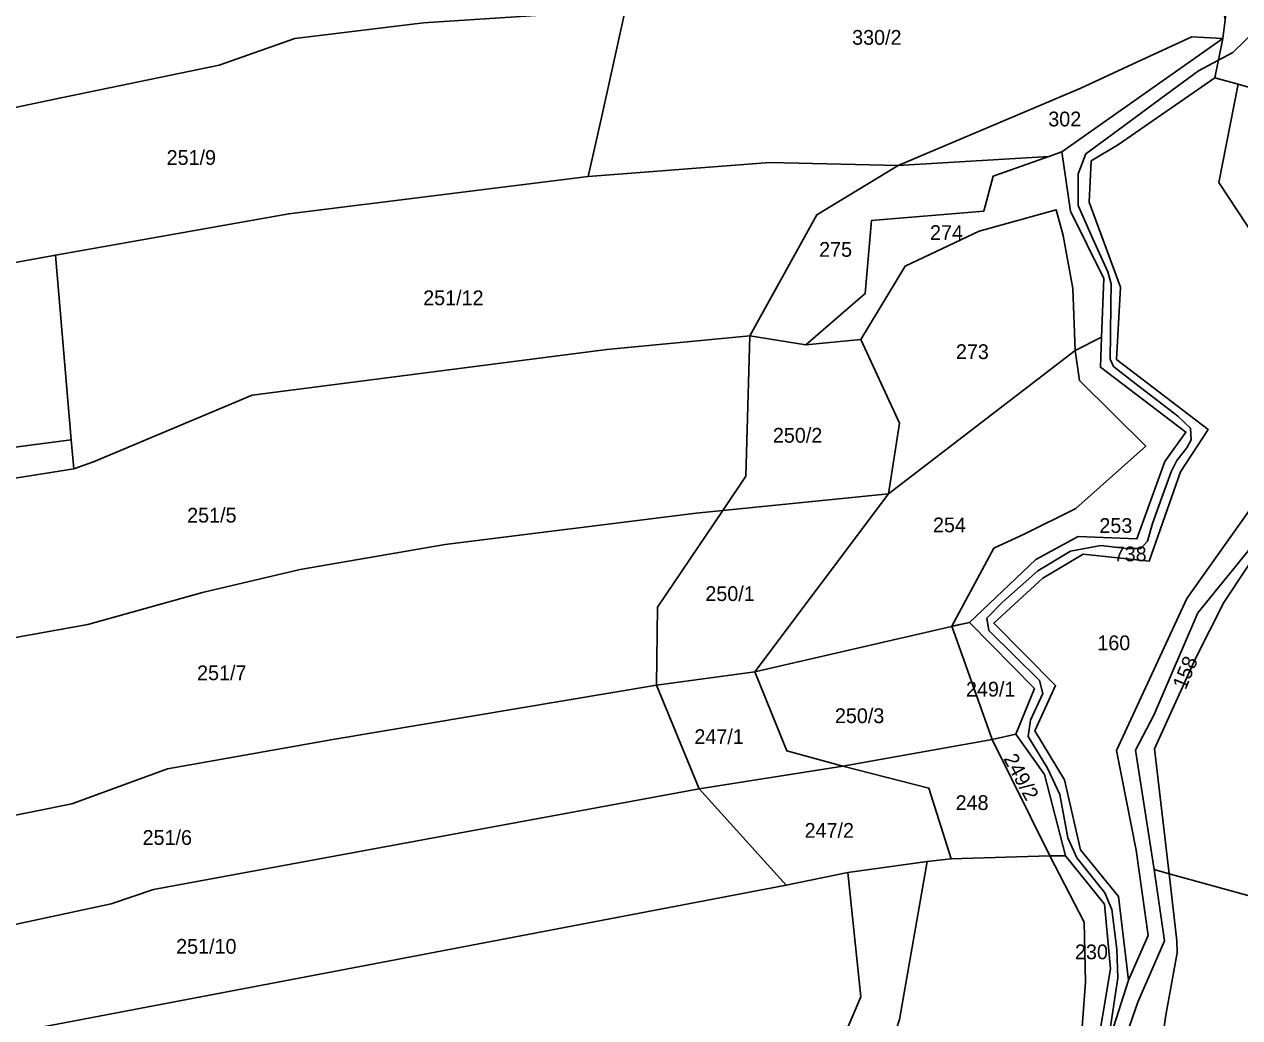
# Model space of a CAD drawing. Extents: x -629983 to -626385, y -1072828 to -1067897.
# Drawn here: x -627910.7 to -627663.6, y -1071057.2 to -1070855.3 of the extents above; entities that cross this region are included whole.
import ezdxf

# ---------------------------------------------------------------- set-up
doc = ezdxf.new("R2010")
doc.units = 0
for name, color, linetype in [('Lesy', 7, 'Continuous'), ('Parcela nároku', 7, 'Continuous'), ('Parcelní číslo', 7, 'Continuous'), ('Plocha PÚ', 7, 'Continuous'), ('Vnitřní obvod_šetřený', 7, 'Continuous'), ('voda', 7, 'Continuous')]:
    doc.layers.add(name, color=color, linetype=linetype)

msp = doc.modelspace()

# ---------------------------------------------------------------- linework, layer by layer
at = {"layer": 'Lesy'}
for p, q in [((-627702.4, -1070882.17), (-627733.04, -1070884.02)), ((-627713.9, -1071000.65), (-627709.08, -1070999.61))]:
    msp.add_line(p, q, dxfattribs=at)
for points in [[(-627763.16, -1070918.66), (-627751.82, -1070920.47), (-627739.75, -1070910.01), (-627738.41, -1070895.18), (-627715.62, -1070893.28), (-627713.72, -1070886.19), (-627702.4, -1070882.17), (-627699.77, -1070881.23)], [(-627768.7, -1070954.14), (-627734.96, -1070950.75), (-627697.03, -1070921.6), (-627691.66, -1070918.93)], [(-627782.13, -1070989.61), (-627762.15, -1070986.91), (-627722.2, -1070977.69), (-627718.53, -1070976.9)], [(-627773.5, -1071010.68), (-627744.25, -1071006.08), (-627713.9, -1071000.65)], [(-627699.02, -1071024.34), (-627702.18, -1071024.34), (-627722.26, -1071024.91), (-627727.14, -1071025.51), (-627743.28, -1071027.73)]]:
    msp.add_lwpolyline(points, dxfattribs=at)
at = {"layer": 'Parcela nároku'}
for points in [[(-627776.03, -1070817.67), (-627781.03, -1070818.65), (-627781.59, -1070821.17), (-627788.59, -1070852.77), (-627793.29, -1070873.99), (-627796.08, -1070886.23), (-627759.08, -1070883.39), (-627733.04, -1070884.02), (-627695.86, -1070868.29), (-627684.37, -1070862.94), (-627673.34, -1070857.87), (-627667.02, -1070858.18), (-627666.57, -1070854.4), (-627669.26, -1070837.49), (-627680.55, -1070832.34), (-627686.39, -1070830.88), (-627692.88, -1070830.18), (-627693.06, -1070825.67), (-627704.19, -1070823.07), (-627730.21, -1070817.05), (-627744.9, -1070815.04)], [(-627801.49, -1070822.34), (-627781.59, -1070821.17), (-627788.59, -1070852.77), (-627795.23, -1070852.8), (-627829.54, -1070855.03), (-627855.66, -1070858.18), (-627871.1, -1070863.63), (-627903.55, -1070870.3), (-627965.1, -1070883.25), (-627964.44, -1070878.78), (-627949.1, -1070853.24), (-627939.64, -1070842.36), (-627915.75, -1070837.66), (-627910.72, -1070836.78), (-627868.6, -1070829.4), (-627844.7, -1070826.54), (-627829.74, -1070827.42), (-627824.59, -1070826.82), (-627818.12, -1070823.77)], [(-627969.54, -1070913.45), (-627965.1, -1070883.25), (-627903.55, -1070870.3), (-627871.1, -1070863.63), (-627855.66, -1070858.18), (-627829.54, -1070855.03), (-627795.23, -1070852.8), (-627788.59, -1070852.77), (-627793.29, -1070873.99), (-627796.08, -1070886.23), (-627856.91, -1070893.83), (-627904.38, -1070902.22), (-627956.41, -1070911.75), (-627967.36, -1070913.5)], [(-627684.37, -1070862.94), (-627673.34, -1070857.87), (-627667.02, -1070858.18), (-627699.77, -1070881.23), (-627702.4, -1070882.17), (-627733.04, -1070884.02), (-627695.86, -1070868.29)], [(-627709.08, -1070999.61), (-627705.31, -1070990.3), (-627718.53, -1070976.9), (-627705.04, -1070964.09), (-627696.41, -1070959.41), (-627684.49, -1070959.86), (-627678.83, -1070944.19), (-627674.53, -1070938.2), (-627691.89, -1070925.02), (-627691.66, -1070918.93), (-627691.21, -1070906.96), (-627697.95, -1070893.27), (-627699.77, -1070881.23), (-627667.02, -1070858.18), (-627668.65, -1070866.2), (-627688.23, -1070879.74), (-627693.76, -1070883.07), (-627694.19, -1070891.48), (-627687.81, -1070908.71), (-627688.65, -1070923.45), (-627670, -1070937.7), (-627675.65, -1070946.29), (-627682.02, -1070964.46), (-627695.43, -1070963.01), (-627703.62, -1070967.89), (-627713.58, -1070977.02), (-627701.03, -1070989.72), (-627705.23, -1070998.92), (-627699.23, -1071008.89), (-627695.93, -1071023.12), (-627688.23, -1071032.59), (-627686.17, -1071049.62), (-627694.72, -1071076.38), (-627689.88, -1071047.31), (-627691.1, -1071034.14), (-627699.02, -1071024.34), (-627703.25, -1071007.78)], [(-627702.4, -1070882.17), (-627699.77, -1070881.23), (-627697.95, -1070893.27), (-627691.21, -1070906.96), (-627691.66, -1070918.93), (-627697.03, -1070921.6), (-627697.5, -1070908.99), (-627699.46, -1070898.26), (-627700.87, -1070893), (-627716.55, -1070897.35), (-627731.61, -1070904.46), (-627740.6, -1070919.36), (-627751.82, -1070920.47), (-627739.75, -1070910.01), (-627738.41, -1070895.18), (-627715.62, -1070893.28), (-627713.72, -1070886.19)], [(-627904.38, -1070902.22), (-627856.91, -1070893.83), (-627796.08, -1070886.23), (-627759.08, -1070883.39), (-627733.04, -1070884.02), (-627749.57, -1070894.02), (-627763.16, -1070918.66), (-627792.28, -1070921.41), (-627864.34, -1070930.66), (-627896.65, -1070944.27), (-627900.65, -1070945.66), (-627901.16, -1070939.77)], [(-627733.04, -1070884.02), (-627702.4, -1070882.17), (-627713.72, -1070886.19), (-627715.62, -1070893.28), (-627738.41, -1070895.18), (-627739.75, -1070910.01), (-627751.82, -1070920.47), (-627763.16, -1070918.66), (-627749.57, -1070894.02)], [(-627699.46, -1070898.26), (-627697.5, -1070908.99), (-627697.03, -1070921.6), (-627734.96, -1070950.75), (-627732.72, -1070936.39), (-627740.6, -1070919.36), (-627731.61, -1070904.46), (-627716.55, -1070897.35), (-627700.87, -1070893)], [(-627904.38, -1070902.22), (-627901.16, -1070939.77), (-627964.42, -1070948.04), (-627965.93, -1070922.44), (-627954.97, -1070920.68), (-627956.41, -1070911.75)], [(-627864.34, -1070930.66), (-627792.28, -1070921.41), (-627763.16, -1070918.66), (-627764.01, -1070947.18), (-627768.7, -1070954.14), (-627774.12, -1070954.69), (-627825.12, -1070961.06), (-627854.63, -1070966.13), (-627874.47, -1070970.81), (-627897.8, -1070977.31), (-627975.92, -1070991.3), (-627973.38, -1070957.36), (-627964.22, -1070955.75), (-627900.65, -1070945.66), (-627896.65, -1070944.27)], [(-627763.16, -1070918.66), (-627751.82, -1070920.47), (-627740.6, -1070919.36), (-627732.72, -1070936.39), (-627734.96, -1070950.75), (-627768.7, -1070954.14), (-627764.01, -1070947.18)], [(-627674.53, -1070938.2), (-627691.89, -1070925.02), (-627691.66, -1070918.93), (-627697.03, -1070921.6), (-627696.16, -1070927.73), (-627682.68, -1070941.05), (-627696.9, -1070953.7), (-627707.27, -1070958.89), (-627713.55, -1070961.76), (-627722.08, -1070977.63), (-627718.53, -1070976.9), (-627705.04, -1070964.09), (-627696.41, -1070959.41), (-627684.49, -1070959.86), (-627678.83, -1070944.19)], [(-627697.03, -1070921.6), (-627696.16, -1070927.73), (-627682.68, -1070941.05), (-627696.9, -1070953.7), (-627707.27, -1070958.89), (-627713.55, -1070961.76), (-627722.08, -1070977.63), (-627722.2, -1070977.69), (-627762.15, -1070986.91), (-627734.96, -1070950.75)], [(-627633.04, -1070934.28), (-627629.23, -1070934.48), (-627610.1, -1070939.85), (-627595.94, -1070943.82), (-627593.56, -1070944.49), (-627607.17, -1070975.87), (-627608.65, -1070982.03), (-627608.85, -1070996.03), (-627589.14, -1071052.37), (-627677.94, -1071028.02), (-627680.89, -1071002.55), (-627672.57, -1070984.19), (-627666.8, -1070972.82), (-627648.36, -1070945.08), (-627646.91, -1070943.45), (-627646.35, -1070936.1)], [(-627901.16, -1070939.77), (-627964.42, -1070948.04), (-627964.22, -1070955.75), (-627900.65, -1070945.66)], [(-627681.06, -1070995.72), (-627672.12, -1070974.94), (-627660.33, -1070960.45), (-627648.36, -1070945.08), (-627666.8, -1070972.82), (-627672.57, -1070984.19), (-627680.89, -1071002.55), (-627677.94, -1071028.02), (-627680.98, -1071027.09), (-627684.77, -1071002.85)], [(-627782.13, -1070989.61), (-627781.92, -1070973.76), (-627768.7, -1070954.14), (-627734.96, -1070950.75), (-627762.15, -1070986.91)], [(-627854.63, -1070966.13), (-627874.47, -1070970.81), (-627897.8, -1070977.31), (-627975.92, -1070991.3), (-627978.19, -1071021.66), (-627978.7, -1071031.04), (-627948.79, -1071023.35), (-627901.04, -1071013.77), (-627881.56, -1071006.67), (-627847.96, -1071000.67), (-627782.13, -1070989.61), (-627781.92, -1070973.76), (-627768.7, -1070954.14), (-627774.12, -1070954.69), (-627825.12, -1070961.06)], [(-627762.15, -1070986.91), (-627722.2, -1070977.69), (-627722.08, -1070977.63), (-627713.9, -1071000.65), (-627744.25, -1071006.08), (-627755.63, -1071003.01)], [(-627705.31, -1070990.3), (-627718.53, -1070976.9), (-627722.08, -1070977.63), (-627713.9, -1071000.65), (-627709.08, -1070999.61)], [(-627782.13, -1070989.61), (-627762.15, -1070986.91), (-627755.63, -1071003.01), (-627744.25, -1071006.08), (-627773.5, -1071010.68)], [(-627773.5, -1071010.68), (-627782.13, -1070989.61), (-627847.96, -1071000.67), (-627881.56, -1071006.67), (-627901.04, -1071013.77), (-627948.79, -1071023.35), (-627978.7, -1071031.04), (-627979.88, -1071052.75), (-627893.02, -1071034.08), (-627884.41, -1071031.17)], [(-627713.9, -1071000.65), (-627702.18, -1071024.34), (-627722.26, -1071024.91), (-627726.76, -1071010.57), (-627744.25, -1071006.08)], [(-627713.9, -1071000.65), (-627709.08, -1070999.61), (-627703.25, -1071007.78), (-627699.02, -1071024.34), (-627702.18, -1071024.34)], [(-627726.76, -1071010.57), (-627722.26, -1071024.91), (-627727.14, -1071025.51), (-627743.28, -1071027.73), (-627755.81, -1071030.27), (-627773.5, -1071010.68), (-627744.25, -1071006.08)], [(-627884.41, -1071031.17), (-627773.5, -1071010.68), (-627755.81, -1071030.27), (-627842.41, -1071046.8), (-627980.99, -1071073.17), (-627979.88, -1071052.75), (-627893.02, -1071034.08)], [(-627732.76, -1071057.61), (-627742.21, -1071086.89), (-627740.95, -1071096.51), (-627718.37, -1071093.78), (-627697.75, -1071094.07), (-627697.26, -1071080.89), (-627694.91, -1071049.98), (-627695.21, -1071037.83), (-627702.18, -1071024.34), (-627722.26, -1071024.91), (-627727.14, -1071025.51)], [(-627694.91, -1071049.98), (-627697.26, -1071080.89), (-627694.72, -1071076.38), (-627689.88, -1071047.31), (-627691.1, -1071034.14), (-627699.02, -1071024.34), (-627702.18, -1071024.34), (-627695.21, -1071037.83)], [(-627990.6, -1071134.13), (-627983.67, -1071096.07), (-627981.04, -1071074.18), (-627980.99, -1071073.17), (-627842.41, -1071046.8), (-627755.81, -1071030.27), (-627743.28, -1071027.73), (-627740.61, -1071053.02), (-627750.22, -1071075.54), (-627752.84, -1071100.75), (-627875.8, -1071126.47), (-627933.16, -1071141.74), (-627995.06, -1071154.04)], [(-627742.21, -1071086.89), (-627740.95, -1071096.51), (-627752.84, -1071100.75), (-627750.22, -1071075.54), (-627740.61, -1071053.02), (-627743.28, -1071027.73), (-627727.14, -1071025.51), (-627732.76, -1071057.61)], [(-627538.56, -1071194.21), (-627524.91, -1071234.88), (-627555.07, -1071238.31), (-627565.67, -1071214.8), (-627570.33, -1071210.92), (-627571.88, -1071209.62), (-627592.75, -1071192.23), (-627608.51, -1071161.77), (-627619.56, -1071140.72), (-627630.41, -1071134.09), (-627635.39, -1071116.68), (-627654.32, -1071103.18), (-627673.05, -1071079.5), (-627680.55, -1071070.62), (-627678.61, -1071056.69), (-627676.31, -1071044.06), (-627676.33, -1071041.64), (-627677.94, -1071028.02), (-627589.14, -1071052.37), (-627581.22, -1071076.02), (-627572.29, -1071106.16), (-627556.31, -1071148.68), (-627546.27, -1071173.51)]]:
    msp.add_lwpolyline(points, close=True, dxfattribs=at)
for points in [[(-627663.44, -1070819.25), (-627665.7, -1070829.55), (-627663.7, -1070828.83), (-627666.57, -1070854.4), (-627667.02, -1070858.18), (-627668.65, -1070866.2), (-627663.91, -1070867.45), (-627660.19, -1070868.57)], [(-627660.36, -1070898.79), (-627667.8, -1070887.49), (-627663.91, -1070867.45), (-627668.65, -1070866.2), (-627688.23, -1070879.74), (-627693.76, -1070883.07), (-627694.19, -1070891.48), (-627687.81, -1070908.71), (-627688.65, -1070923.45), (-627670, -1070937.7), (-627675.65, -1070946.29), (-627682.02, -1070964.46), (-627695.43, -1070963.01), (-627703.62, -1070967.89), (-627713.58, -1070977.02), (-627701.03, -1070989.72), (-627705.23, -1070998.92), (-627699.23, -1071008.89), (-627695.93, -1071023.12), (-627688.23, -1071032.59), (-627686.17, -1071049.62), (-627682.2, -1071040.54), (-627684.63, -1071023.21), (-627688.6, -1071002.91), (-627674.3, -1070972.05), (-627652.45, -1070941.16)], [(-627660.36, -1070898.79), (-627667.8, -1070887.49), (-627663.91, -1070867.45), (-627660.19, -1070868.57)], [(-627694.72, -1071076.38), (-627686.17, -1071049.62), (-627682.2, -1071040.54), (-627684.63, -1071023.21), (-627688.6, -1071002.91), (-627674.3, -1070972.05), (-627652.45, -1070941.16)], [(-627660.33, -1070960.45), (-627672.12, -1070974.94), (-627681.06, -1070995.72), (-627684.77, -1071002.85), (-627680.98, -1071027.09), (-627678.87, -1071041.58), (-627684.26, -1071054.09), (-627691.54, -1071074.97)], [(-627691.54, -1071074.97), (-627684.26, -1071054.09), (-627678.87, -1071041.58), (-627680.98, -1071027.09), (-627677.94, -1071028.02), (-627676.33, -1071041.64), (-627676.31, -1071044.06), (-627678.61, -1071056.69), (-627680.55, -1071070.62)]]:
    msp.add_lwpolyline(points, dxfattribs=at)
at = {"layer": 'Plocha PÚ'}
msp.add_lwpolyline([(-627666.57, -1070854.4), (-627667.02, -1070858.18), (-627673.34, -1070857.87), (-627684.37, -1070862.94), (-627695.86, -1070868.29), (-627733.04, -1070884.02), (-627759.08, -1070883.39), (-627796.08, -1070886.23), (-627793.29, -1070873.99), (-627788.59, -1070852.77)], dxfattribs=at)
msp.add_lwpolyline([(-627904.38, -1070902.22), (-627901.16, -1070939.77), (-627964.42, -1070948.04), (-627965.93, -1070922.44), (-627967.36, -1070913.5), (-627956.41, -1070911.75)], close=True, dxfattribs=at)
at = {"layer": 'Vnitřní obvod_šetřený'}
for p, q in [((-627793.29, -1070873.99), (-627788.59, -1070852.77)), ((-627666.57, -1070854.4), (-627667.02, -1070858.18)), ((-627673.34, -1070857.87), (-627684.37, -1070862.94)), ((-627667.02, -1070858.18), (-627673.34, -1070857.87)), ((-627684.37, -1070862.94), (-627695.86, -1070868.29)), ((-627695.86, -1070868.29), (-627733.04, -1070884.02)), ((-627796.08, -1070886.23), (-627793.29, -1070873.99)), ((-627759.08, -1070883.39), (-627796.08, -1070886.23)), ((-627733.04, -1070884.02), (-627759.08, -1070883.39)), ((-627956.41, -1070911.75), (-627904.38, -1070902.22)), ((-627904.38, -1070902.22), (-627901.16, -1070939.77)), ((-627901.16, -1070939.77), (-627964.42, -1070948.04))]:
    msp.add_line(p, q, dxfattribs=at)
at = {"layer": 'voda'}
msp.add_lwpolyline([(-627689.82, -1071059.06), (-627688.35, -1071049.16), (-627688.58, -1071043.29), (-627689.59, -1071035.23), (-627691.01, -1071031.83), (-627696.72, -1071024.76), (-627698.52, -1071020.65), (-627700.12, -1071011.85), (-627702.69, -1071006.52), (-627706.6, -1071000.04), (-627706.09, -1070996.76), (-627703.58, -1070991.36), (-627704.29, -1070988.67), (-627709.43, -1070983.59), (-627714.57, -1070978.51), (-627715.01, -1070976.01), (-627711.8, -1070972.8), (-627704.61, -1070966.4), (-627697.97, -1070962.4), (-627691.8, -1070961.26), (-627686.63, -1070961.89), (-627683.66, -1070961.85), (-627682.3, -1070960.38), (-627681.31, -1070956.75), (-627679.42, -1070951.51), (-627677.53, -1070946.27), (-627676.36, -1070943.94), (-627674.36, -1070941.38), (-627673.42, -1070939.76), (-627673.59, -1070937.39), (-627676.19, -1070934.98), (-627680.55, -1070931.6), (-627684.91, -1070928.22), (-627689.27, -1070924.84), (-627689.94, -1070923.36), (-627689.87, -1070918.28), (-627689.79, -1070912.24), (-627689.73, -1070908.07), (-627690.39, -1070905.63), (-627693.41, -1070898.89), (-627696.43, -1070892.15), (-627696.44, -1070885.67), (-627694.87, -1070881.62), (-627687.23, -1070876), (-627679.59, -1070870.38), (-627671.95, -1070864.76), (-627664.98, -1070861.05), (-627660.03, -1070856.22)], dxfattribs=at)

# ---------------------------------------------------------------- texts
at = {"layer": 'Parcelní číslo'}
for s, p in [('330/2', (-627742.38, -1070859.47)), ('302', (-627702.5, -1070876.06)), ('251/9', (-627881.75, -1070883.88)), ('274', (-627726.54, -1070899.14)), ('275', (-627749.09, -1070902.57)), ('251/12', (-627829.59, -1070912.4)), ('273', (-627721.28, -1070923.35)), ('250/2', (-627758.49, -1070940.35)), ('251/5', (-627877.58, -1070956.59)), ('254', (-627725.94, -1070958.56)), ('253', (-627692.11, -1070958.69)), ('738', (-627689.19, -1070964.46)), ('250/1', (-627772.22, -1070972.53)), ('160', (-627692.53, -1070982.53)), ('251/7', (-627875.56, -1070988.63)), ('249/1', (-627719.23, -1070991.95)), ('250/3', (-627745.88, -1070997.35)), ('247/1', (-627774.45, -1071001.6)), ('248', (-627721.34, -1071015.01)), ('247/2', (-627752.05, -1071020.66)), ('251/6', (-627886.64, -1071022.1)), ('251/10', (-627879.82, -1071044.23)), ('230', (-627697.07, -1071045.35))]:
    msp.add_text(s, height=3, dxfattribs=at).set_placement(p)
for s, rotation, p in [('158', 67.7298, (-627674.56, -1070990.73)), ('249/2', 298.4294, (-627711.71, -1071004.56))]:
    msp.add_text(s, height=3, rotation=rotation, dxfattribs=at).set_placement(p)

doc.saveas('drawing.dxf')
